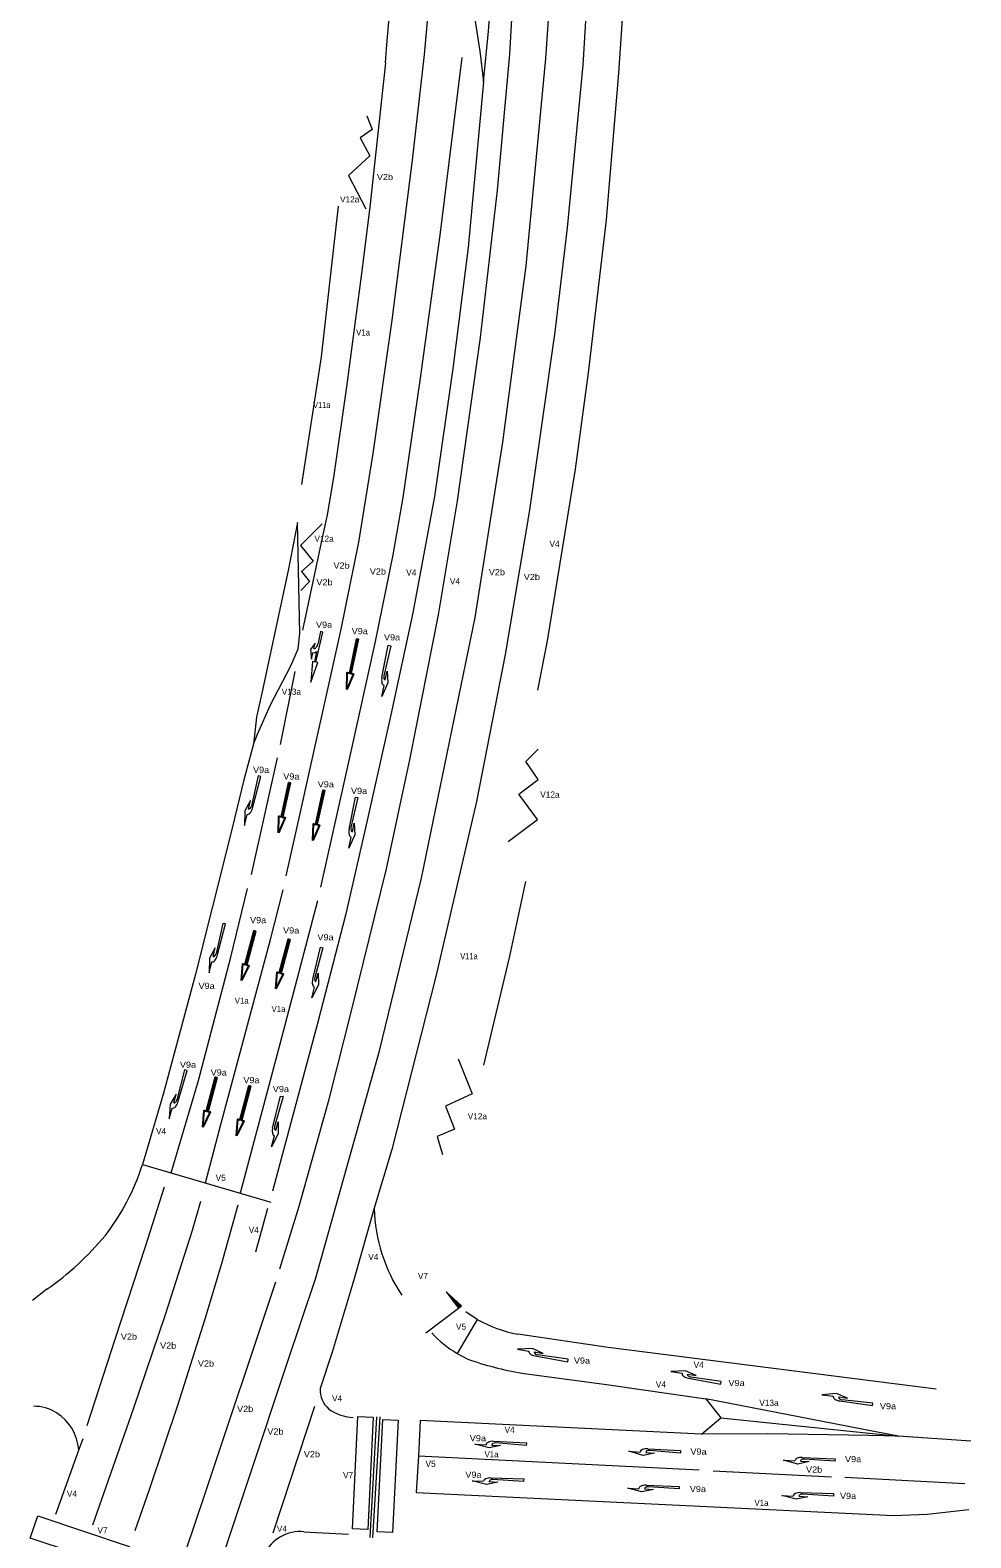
# Model space of a CAD drawing. Extents: x -598770 to -598612, y -1162818 to -1162391.
# Drawn here: x -598703.8 to -598612.3, y -1162656.8 to -1162510.2 of the extents above; entities that cross this region are included whole.
import ezdxf

# ---------------------------------------------------------------- set-up
doc = ezdxf.new("R2010")
doc.units = 0
doc.header["$LTSCALE"] = 0.24
for name, color, linetype, lineweight in [('1', 7, 'Continuous', 25), ('47', 7, 'Continuous', 13), ('48', 7, 'Continuous', 13)]:
    doc.layers.add(name, color=color, linetype=linetype, lineweight=lineweight)

msp = doc.modelspace()

# ---------------------------------------------------------------- hatches: boundary and pattern name
at = {"layer": '47'}
msp.add_hatch(color=256, dxfattribs=at).paths.add_polyline_path([(-598663.33, -1162632.866), (-598662.126, -1162634.456), (-598661.831, -1162634.21)])

# ---------------------------------------------------------------- linework, layer by layer
at = {"layer": '1'}
for points in [[(-598672.971, -1162574.273), (-598672.934, -1162572.645), (-598672.699, -1162572.695), (-598671.999, -1162569.368), (-598671.881, -1162569.392), (-598672.582, -1162572.719), (-598672.347, -1162572.769)], [(-598679.623, -1162588.236), (-598679.576, -1162586.608), (-598679.342, -1162586.659), (-598678.619, -1162583.337), (-598678.501, -1162583.363), (-598679.224, -1162586.685), (-598678.99, -1162586.736)], [(-598676.283, -1162588.976), (-598676.236, -1162587.348), (-598676.002, -1162587.399), (-598675.279, -1162584.077), (-598675.161, -1162584.103), (-598675.884, -1162587.425), (-598675.65, -1162587.476)], [(-598683.223, -1162602.59), (-598683.099, -1162600.967), (-598682.867, -1162601.029), (-598681.988, -1162597.744), (-598681.872, -1162597.776), (-598682.751, -1162601.06), (-598682.519, -1162601.122)], [(-598679.883, -1162603.4), (-598679.759, -1162601.777), (-598679.527, -1162601.839), (-598678.648, -1162598.554), (-598678.532, -1162598.586), (-598679.411, -1162601.87), (-598679.179, -1162601.932)], [(-598686.968, -1162616.841), (-598686.846, -1162615.218), (-598686.614, -1162615.28), (-598685.738, -1162611.995), (-598685.622, -1162612.025), (-598686.498, -1162615.311), (-598686.266, -1162615.372)], [(-598683.698, -1162617.691), (-598683.576, -1162616.068), (-598683.344, -1162616.13), (-598682.468, -1162612.845), (-598682.352, -1162612.875), (-598683.228, -1162616.161), (-598682.996, -1162616.222)]]:
    msp.add_lwpolyline(points, close=True, dxfattribs=at)
at = {"layer": '47'}
for p, q in [((-598669.23, -1162513.32), (-598670.74, -1162527.36)), ((-598679.44, -1162579.63), (-598678.01, -1162572.54)), ((-598669.581, -1162574.954), (-598669.354, -1162573.878)), ((-598682.24, -1162592.26), (-598679.73, -1162580.94)), ((-598682.935, -1162587.5), (-598682.677, -1162586.431)), ((-598672.789, -1162589.72), (-598672.556, -1162588.645)), ((-598686.375, -1162601.85), (-598686.117, -1162600.781)), ((-598676.395, -1162604.283), (-598676.117, -1162603.219)), ((-598690.238, -1162616.054), (-598689.948, -1162614.993)), ((-598680.3, -1162618.758), (-598680.017, -1162617.695)), ((-598692.85, -1162620.47), (-598680.36, -1162624.14)), ((-598683.59, -1162624.42), (-598685.21, -1162630.23)), ((-598680.71, -1162624.76), (-598681.86, -1162629.01)), ((-598702.14, -1162632.62), (-598703.55, -1162633.7)), ((-598665.308, -1162636.856), (-598662.126, -1162634.456)), ((-598660.32, -1162635.54), (-598662.25, -1162638.85)), ((-598660.32, -1162635.54), (-598661.42, -1162634.81)), ((-598656.378, -1162638.447), (-598655.292, -1162638.623)), ((-598662.25, -1162638.85), (-598661.29, -1162639.38)), ((-598641.481, -1162640.597), (-598640.396, -1162640.779)), ((-598626.791, -1162642.877), (-598625.7, -1162643.017)), ((-598670.108, -1162645.016), (-598670.76, -1162656.752)), ((-598670.458, -1162656.782), (-598669.752, -1162645.023)), ((-598638.51, -1162646.72), (-598665.86, -1162645.39)), ((-598612.32, -1162647.38), (-598619.36, -1162646.91)), ((-598660.539, -1162647.667), (-598659.441, -1162647.733)), ((-598645.559, -1162648.367), (-598644.461, -1162648.447)), ((-598638.72, -1162650.21), (-598666, -1162648.86)), ((-598637.36, -1162650.28), (-598625.85, -1162650.86)), ((-598630.529, -1162649.241), (-598629.431, -1162649.302)), ((-598660.799, -1162651.237), (-598659.7, -1162651.292)), ((-598624.57, -1162650.89), (-598612.9, -1162651.52)), ((-598645.679, -1162651.952), (-598644.58, -1162652.009)), ((-598630.679, -1162652.671), (-598629.58, -1162652.724)), ((-598677.15, -1162656.2), (-598672.83, -1162656.43))]:
    msp.add_line(p, q, dxfattribs=at)
for points in [[(-598678.87, -1162592.39), (-598677.52, -1162586.33), (-598673.52, -1162568.4), (-598671.82, -1162559.94), (-598670.41, -1162551.33), (-598668.56, -1162538.37), (-598666.59, -1162522.8), (-598665.43, -1162512.51), (-598664.23, -1162499.31), (-598663.42, -1162479.81), (-598663.05, -1162465.06), (-598662.73, -1162447.04), (-598662.35, -1162421.85), (-598661.61, -1162391.33)], [(-598679.49, -1162630.64), (-598677.61, -1162624.52), (-598674.71, -1162614.13), (-598672.49, -1162605.39), (-598669.14, -1162591.74), (-598666.82, -1162580.97), (-598664.07, -1162567.02), (-598662.23, -1162555.94), (-598659.99, -1162540.04), (-598658.35, -1162525.71), (-598657.15, -1162512.49), (-598656.01, -1162492.63), (-598655.18, -1162469.38), (-598654.56, -1162443.12), (-598653.84, -1162397.63)], [(-598685.18, -1162659.01), (-598682.44, -1162650.81), (-598678.78, -1162639.81), (-598676.01, -1162631.49), (-598669.81, -1162609.43), (-598665.71, -1162592.63), (-598660.52, -1162567.28), (-598657.82, -1162550.24), (-598655.55, -1162533.08), (-598653.64, -1162512.9), (-598653.24, -1162507.21), (-598652.17, -1162486.96), (-598650.81, -1162443.8), (-598650.17, -1162405.3)], [(-598646.54, -1162514.33), (-598645.68, -1162501.34), (-598645.05, -1162489.31), (-598644.56, -1162473.7), (-598643.88, -1162444.91), (-598643.66, -1162430.52), (-598643.5, -1162416.45), (-598643.38, -1162413.74)], [(-598647.05, -1162439.3), (-598647.13, -1162443.65), (-598647.86, -1162469.34), (-598648.56, -1162488.8), (-598650.03, -1162513.56), (-598651.56, -1162529.37), (-598652.75, -1162539.5), (-598655.24, -1162557.05), (-598657.58, -1162570.89), (-598660.39, -1162585.19), (-598664.32, -1162602.18), (-598668.6, -1162619.03), (-598670.31, -1162624.74)], [(-598669.23, -1162513.32), (-598669.13, -1162511.96), (-598667.99, -1162498.64), (-598668.42, -1162494.66), (-598668.51, -1162493.83), (-598670.21, -1162477.32), (-598670.5, -1162473.95), (-598670.55, -1162470), (-598670.35, -1162452.54)], [(-598675.52, -1162593.51), (-598672.68, -1162580.9), (-598670.21, -1162569.62), (-598668.47, -1162561.18), (-598667.49, -1162555.61), (-598665.84, -1162544.22), (-598663.91, -1162530.08), (-598661.76, -1162512.81)], [(-598659.7, -1162515.17), (-598661.2, -1162531.28), (-598662.68, -1162543.06), (-598664.45, -1162555.5), (-598666.55, -1162566.81), (-598668.69, -1162576.75), (-598670.99, -1162587.01), (-598673.12, -1162596.24), (-598675.8, -1162606.65), (-598680.21, -1162623.08)], [(-598654.4, -1162574.34), (-598653.46, -1162569.54), (-598650.75, -1162552.85), (-598649.48, -1162543.49), (-598647.74, -1162528.61), (-598647.6, -1162527.02), (-598646.54, -1162514.33)], [(-598670.74, -1162527.36), (-598671.57, -1162533.81), (-598673.02, -1162544.84), (-598674.29, -1162553.67), (-598674.9, -1162557.28)], [(-598674.9, -1162557.28), (-598675.37, -1162559.52), (-598677.29, -1162568.52)], [(-598676.476, -1162573.57), (-598675.815, -1162571.666), (-598675.986, -1162571.63), (-598675.312, -1162568.706), (-598675.434, -1162568.68), (-598675.556, -1162568.654), (-598675.778, -1162569.783)], [(-598676.19, -1162570.308), (-598676.075, -1162569.77), (-598676.515, -1162570.392), (-598676.409, -1162571.335), (-598676.274, -1162570.7)], [(-598675.932, -1162570.573), (-598676.133, -1162571.599), (-598676.304, -1162571.562), (-598676.476, -1162573.57)], [(-598669.573, -1162573.116), (-598668.962, -1162569.974), (-598668.718, -1162570.026), (-598669.388, -1162572.951)], [(-598669.242, -1162573.349), (-598669.064, -1162572.508), (-598668.998, -1162573.646), (-598669.581, -1162574.954)], [(-598682.06, -1162579.59), (-598683, -1162583.08), (-598684.14, -1162587.77), (-598686.06, -1162595.52), (-598687.69, -1162601.98), (-598690.81, -1162613.54), (-598692.85, -1162620.47)], [(-598682.151, -1162585.838), (-598681.348, -1162582.739), (-598681.592, -1162582.681), (-598682.247, -1162585.609)], [(-598682.55, -1162585.906), (-598682.348, -1162585.07), (-598682.898, -1162586.069), (-598682.935, -1162587.5)], [(-598672.77, -1162587.882), (-598672.142, -1162584.743), (-598671.898, -1162584.797), (-598672.584, -1162587.717)], [(-598672.441, -1162588.117), (-598672.258, -1162587.277), (-598672.199, -1162588.415), (-598672.789, -1162589.72)], [(-598690.07, -1162621.29), (-598687.4, -1162612.31), (-598684.25, -1162600.33), (-598682.63, -1162593.63)], [(-598686.73, -1162622.27), (-598685.23, -1162616.58), (-598680.4, -1162598.6), (-598679.18, -1162593.78)], [(-598675.82, -1162594.82), (-598679.49, -1162608.78), (-598683.36, -1162623.26)], [(-598685.591, -1162600.188), (-598684.788, -1162597.089), (-598685.032, -1162597.031), (-598685.687, -1162599.959)], [(-598685.99, -1162600.256), (-598685.788, -1162599.42), (-598686.338, -1162600.419), (-598686.375, -1162601.85)], [(-598676.299, -1162602.448), (-598675.541, -1162599.338), (-598675.299, -1162599.402), (-598676.107, -1162602.291)], [(-598675.98, -1162602.697), (-598675.762, -1162601.865), (-598675.75, -1162603.005), (-598676.395, -1162604.283)], [(-598689.404, -1162614.416), (-598688.509, -1162611.343), (-598688.751, -1162611.277), (-598689.494, -1162614.184)], [(-598689.805, -1162614.472), (-598689.579, -1162613.642), (-598690.158, -1162614.624), (-598690.238, -1162616.054)], [(-598680.195, -1162616.923), (-598679.421, -1162613.818), (-598679.179, -1162613.882), (-598680.002, -1162616.768)], [(-598679.877, -1162617.174), (-598679.655, -1162616.343), (-598679.649, -1162617.483), (-598680.3, -1162618.758)], [(-598698.24, -1162645.87), (-598695.48, -1162637.38), (-598692.57, -1162628.46), (-598690.7, -1162622.66)], [(-598687.22, -1162624.09), (-598688.01, -1162626.91), (-598690.63, -1162635.09), (-598693.75, -1162644.29), (-598697.72, -1162655.57)], [(-598670.31, -1162624.74), (-598672.25, -1162631.48), (-598672.65, -1162632.89)], [(-598685.21, -1162630.23), (-598686.79, -1162635.51), (-598689.42, -1162643.81), (-598692.15, -1162652.01), (-598693.6, -1162656.11)], [(-598688.64, -1162658.06), (-598686.79, -1162652.59), (-598679.89, -1162631.9)], [(-598672.65, -1162632.89), (-598674.4, -1162638.73), (-598675.59, -1162642.28)], [(-598615.7, -1162642.34), (-598647.59, -1162638.27), (-598656.35, -1162636.98)], [(-598654.759, -1162638.709), (-598653.91, -1162638.846), (-598654.948, -1162638.374), (-598656.378, -1162638.447)], [(-598654.661, -1162639.101), (-598651.51, -1162639.663), (-598651.47, -1162639.417), (-598654.44, -1162638.988)], [(-598655.96, -1162640.77), (-598647.73, -1162641.87), (-598638.08, -1162643.28)], [(-598639.864, -1162640.868), (-598639.016, -1162641.011), (-598640.051, -1162640.533), (-598641.481, -1162640.597)], [(-598639.767, -1162641.261), (-598636.62, -1162641.844), (-598636.579, -1162641.597), (-598639.546, -1162641.15)], [(-598625.165, -1162643.086), (-598624.312, -1162643.195), (-598625.365, -1162642.758), (-598626.791, -1162642.877)], [(-598680.14, -1162656.31), (-598679.23, -1162653.55), (-598676.09, -1162643.98)], [(-598625.053, -1162643.475), (-598621.886, -1162643.934), (-598621.854, -1162643.686), (-598624.836, -1162643.355)], [(-598665.86, -1162645.39), (-598666, -1162648.86), (-598666.23, -1162652.38)], [(-598698.65, -1162647.17), (-598699.05, -1162648.21), (-598701.29, -1162654.52)], [(-598658.902, -1162647.766), (-598658.044, -1162647.818), (-598659.16, -1162648.051), (-598660.539, -1162647.667)], [(-598658.72, -1162647.404), (-598655.522, -1162647.545), (-598655.538, -1162647.795), (-598658.529, -1162647.563)], [(-598643.923, -1162648.486), (-598643.065, -1162648.548), (-598644.184, -1162648.768), (-598645.559, -1162648.367)], [(-598643.736, -1162648.126), (-598640.541, -1162648.305), (-598640.559, -1162648.555), (-598643.548, -1162648.287)], [(-598628.891, -1162649.332), (-598628.033, -1162649.38), (-598629.148, -1162649.619), (-598630.529, -1162649.241)], [(-598628.711, -1162648.97), (-598625.513, -1162649.095), (-598625.527, -1162649.345), (-598628.52, -1162649.128)], [(-598659.161, -1162651.32), (-598658.302, -1162651.363), (-598659.416, -1162651.607), (-598660.799, -1162651.237)], [(-598658.982, -1162650.956), (-598655.784, -1162651.065), (-598655.796, -1162651.315), (-598658.79, -1162651.113)], [(-598643.862, -1162651.673), (-598640.664, -1162651.785), (-598640.676, -1162652.035), (-598643.67, -1162651.83)], [(-598666.23, -1162652.38), (-598623.19, -1162654.47), (-598619.84, -1162654.62), (-598616.55, -1162654.49), (-598612.52, -1162654.04)], [(-598644.041, -1162652.037), (-598643.182, -1162652.081), (-598644.296, -1162652.324), (-598645.679, -1162651.952)], [(-598629.04, -1162652.749), (-598628.181, -1162652.79), (-598629.295, -1162653.038), (-598630.679, -1162652.671)], [(-598628.863, -1162652.385), (-598625.664, -1162652.485), (-598625.676, -1162652.735), (-598628.67, -1162652.542)]]:
    msp.add_lwpolyline(points, dxfattribs=at)
for points in [[(-598659.74, -1162480.57), (-598660.04, -1162488.91), (-598660.27, -1162492.9), (-598660.68, -1162500.88), (-598661.01, -1162505.9), (-598660.06, -1162512.2), (-598659.7, -1162515.17), (-598659.2, -1162510.24), (-598658.47, -1162500.66), (-598659.18, -1162488.38)], [(-598677.77, -1162558.05), (-598678.7, -1162562.71), (-598680.08, -1162569.19), (-598681.19, -1162574.36), (-598681.77, -1162576.97), (-598682.06, -1162579.59), (-598681.68, -1162578.63), (-598680.4, -1162575.78), (-598678.44, -1162571.97), (-598677.71, -1162570.33), (-598677.55, -1162568.82)], [(-598663.33, -1162632.866), (-598662.126, -1162634.456), (-598661.831, -1162634.21)], [(-598636.63, -1162645.12), (-598619.36, -1162646.91), (-598622.22, -1162646.34), (-598638.08, -1162643.28)], [(-598671.918, -1162644.987), (-598670.414, -1162645.064), (-598670.946, -1162655.991), (-598672.441, -1162655.914)], [(-598669.498, -1162645.276), (-598667.994, -1162645.353), (-598668.526, -1162656.28), (-598670.021, -1162656.203)], [(-598636.63, -1162645.12), (-598619.36, -1162646.91), (-598622.23, -1162646.83), (-598632.06, -1162646.69), (-598638.51, -1162646.72)], [(-598703.027, -1162654.647), (-598694.128, -1162657.617), (-598694.848, -1162659.777), (-598703.766, -1162656.807)]]:
    msp.add_lwpolyline(points, close=True, dxfattribs=at)
for centre, radius, start, end in [((-598713.6451, -1162613.9876), 21.7821, 321.95997, 342.6864), ((-598654.5208, -1162624.3927), 15.793, 181.26003, 213.8948), ((-598719.1139, -1162608.5441), 29.4578, 305.18436, 320.17543), ((-598653.8954, -1162624.0202), 13.1903, 240.8515, 259.27502), ((-598657.5058, -1162630.4657), 9.6334, 221.50762, 240.49704), ((-598651.0983, -1162611.2135), 29.9537, 250.10791, 260.6591), ((-598673.0575, -1162642.3653), 2.5339, 178.07143, 228.39559), ((-598703.3569, -1162647.9816), 3.9827, 57.03786, 91.3394), ((-598672.1663, -1162640.6517), 4.4321, 234.50108, 267.62512), ((-598703.6699, -1162648.5529), 4.6326, 4.24542, 57.63488), ((-598677.536, -1162659.9634), 3.7832, 84.1441, 155.92246)]:
    msp.add_arc(centre, radius, start, end, dxfattribs=at)
for centre, major_axis, ratio, start_param, end_param in [((-598676.2317, -1162570.5042), (0.3012, -0.0642), 0.649351, 4.71238898, 6.28318531), ((-598676.0649, -1162569.7217), (0.1251, 0.5868), 0.49, 3.14159265, 4.71238898), ((-598669.2086, -1162573.1926), (-0.1449, -0.6848), 0.531429, 4.71238898, 6.28318531), ((-598669.1672, -1162572.9969), (-0.0745, -0.3522), 0.625, 4.71238898, 6.28318531), ((-598682.4657, -1162585.556), (0.0845, 0.3499), 0.625, 3.14159265, 4.71238898), ((-598682.5126, -1162585.7504), (0.1642, 0.6805), 0.531429, 3.14159265, 4.71238898), ((-598672.4067, -1162587.9605), (-0.1488, -0.684), 0.531429, 4.71238898, 6.28318531), ((-598672.3642, -1162587.765), (-0.0765, -0.3518), 0.625, 4.71238898, 6.28318531), ((-598685.9526, -1162600.1004), (0.1642, 0.6805), 0.531429, 3.14159265, 4.71238898), ((-598685.9057, -1162599.906), (0.0845, 0.3499), 0.625, 3.14159265, 4.71238898), ((-598675.9392, -1162602.5416), (-0.1771, -0.6772), 0.531429, 4.71238898, 6.28318531), ((-598675.8886, -1162602.3481), (-0.0911, -0.3483), 0.625, 4.71238898, 6.28318531), ((-598689.7634, -1162614.3177), (0.1846, 0.6752), 0.531429, 3.14159265, 4.71238898), ((-598689.7107, -1162614.1248), (0.0949, 0.3473), 0.625, 3.14159265, 4.71238898), ((-598679.8357, -1162617.0188), (0.1806, 0.6763), 0.531429, 1.57079633, 3.14159265), ((-598679.7841, -1162616.8256), (0.0929, 0.3478), 0.625, 1.57079633, 3.14159265), ((-598654.6015, -1162638.7339), (0.6911, -0.1115), 0.531429, 3.14159265, 4.71238898), ((-598654.404, -1162638.7658), (0.3554, -0.0574), 0.625, 3.14159265, 4.71238898), ((-598639.706, -1162640.8945), (0.6903, -0.1159), 0.531429, 3.14159265, 4.71238898), ((-598639.5088, -1162640.9276), (0.355, -0.0596), 0.625, 3.14159265, 4.71238898), ((-598625.0061, -1162643.1059), (0.6943, -0.0889), 0.531429, 3.14159265, 4.71238898), ((-598624.8077, -1162643.1313), (0.3571, -0.0457), 0.625, 3.14159265, 4.71238898), ((-598658.7421, -1162647.776), (-0.6987, 0.0424), 0.531429, 4.71238898, 6.28318531), ((-598658.5424, -1162647.7881), (-0.3593, 0.0218), 0.625, 4.71238898, 6.28318531), ((-598643.7631, -1162648.4975), (0.6982, -0.0507), 0.531429, 1.57079633, 3.14159265), ((-598643.5636, -1162648.512), (0.3591, -0.0261), 0.625, 1.57079633, 3.14159265), ((-598628.7315, -1162649.3416), (-0.6989, 0.039), 0.531429, 4.71238898, 6.28318531), ((-598628.5318, -1162649.3527), (-0.3594, 0.02), 0.625, 4.71238898, 6.28318531), ((-598659.0008, -1162651.328), (0.6991, -0.0354), 0.531429, 1.57079633, 3.14159265), ((-598658.8011, -1162651.3381), (0.3595, -0.0182), 0.625, 1.57079633, 3.14159265), ((-598643.881, -1162652.045), (-0.6991, 0.036), 0.531429, 4.71238898, 6.28318531), ((-598643.6812, -1162652.0553), (-0.3595, 0.0185), 0.625, 4.71238898, 6.28318531), ((-598628.8804, -1162652.7572), (0.6992, -0.0334), 0.531429, 1.57079633, 3.14159265), ((-598628.6807, -1162652.7667), (0.3596, -0.0172), 0.625, 1.57079633, 3.14159265)]:
    msp.add_ellipse(centre, major_axis=major_axis, ratio=ratio, start_param=start_param, end_param=end_param, dxfattribs=at)
at = {"layer": '48'}
for points in [[(-598671.04, -1162518.49), (-598670.52, -1162519.82), (-598671.67, -1162520.63), (-598670.74, -1162522.39), (-598672.81, -1162524.29), (-598671.15, -1162527.54)], [(-598673.83, -1162527.28), (-598675.49, -1162541.94), (-598677.39, -1162554.36)], [(-598675.38, -1162558.16), (-598677.49, -1162560.27), (-598676.24, -1162561.79), (-598677.38, -1162562.82), (-598676.62, -1162563.79), (-598677.44, -1162564.66)], [(-598657.3, -1162589.08), (-598654.44, -1162586.91), (-598656.27, -1162584.45), (-598654.38, -1162583.05), (-598655.59, -1162581.3), (-598654.38, -1162580.07)], [(-598659.67, -1162610.82), (-598657.14, -1162600.21), (-598655.57, -1162592.96)], [(-598662.17, -1162610.21), (-598660.8, -1162613.61), (-598663.38, -1162614.81), (-598662.52, -1162617.05), (-598664.2, -1162617.75), (-598663.67, -1162619.52)]]:
    msp.add_lwpolyline(points, dxfattribs=at)

# ---------------------------------------------------------------- texts
at = {"layer": '47'}
for s, width, p in [('V2b', 1.1, (-598670.06, -1162524.74)), ('V1a', 0.95, (-598672.08, -1162539.86)), ('V2b', 1.1, (-598674.28, -1162562.53)), ('V2b', 1.1, (-598675.94, -1162564.15)), ('V2b', 1.1, (-598670.75, -1162563.1)), ('V2b', 1.1, (-598659.18, -1162563.17)), ('V2b', 1.1, (-598655.78, -1162563.64)), ('V9a', 1.1, (-598675.98, -1162568.28)), ('V9a', 1.1, (-598672.51, -1162568.91)), ('V9a', 1.1, (-598669.37, -1162569.51)), ('V9a', 1.1, (-598682.1, -1162582.4)), ('V9a', 1.1, (-598679.16, -1162583.04)), ('V9a', 1.1, (-598675.81, -1162583.8)), ('V9a', 1.1, (-598672.58, -1162584.44)), ('V9a', 1.1, (-598682.39, -1162597.01)), ('V9a', 1.1, (-598679.18, -1162598.01)), ('V9a', 1.1, (-598675.84, -1162598.68)), ('V9a', 1.1, (-598687.4, -1162603.41)), ('V1a', 0.95, (-598683.88, -1162604.85)), ('V1a', 0.95, (-598680.3, -1162605.65)), ('V9a', 1.1, (-598689.21, -1162611.07)), ('V9a', 1.1, (-598686.22, -1162611.83)), ('V9a', 1.1, (-598683.04, -1162612.57)), ('V9a', 1.1, (-598680.18, -1162613.44)), ('V2b', 1.1, (-598694.95, -1162637.52)), ('V2b', 1.1, (-598691.14, -1162638.39)), ('V2b', 1.1, (-598687.46, -1162640.13)), ('V9a', 1.1, (-598650.91, -1162639.85)), ('V9a', 1.1, (-598635.88, -1162642.03)), ('V2b', 1.1, (-598683.65, -1162644.55)), ('V9a', 1.1, (-598621.16, -1162644.28)), ('V2b', 1.1, (-598680.71, -1162646.75)), ('V9a', 1.1, (-598661.03, -1162647.4)), ('V2b', 1.1, (-598677.16, -1162648.96)), ('V1a', 0.95, (-598659.59, -1162648.96)), ('V9a', 1.1, (-598639.58, -1162648.7)), ('V9a', 1.1, (-598624.55, -1162649.43)), ('V2b', 1.1, (-598628.34, -1162650.45)), ('V9a', 1.1, (-598661.46, -1162650.95)), ('V9a', 1.1, (-598639.64, -1162652.34)), ('V1a', 0.95, (-598633.35, -1162653.69)), ('V9a', 1.1, (-598625.04, -1162653.01))]:
    msp.add_text(s, height=0.6, dxfattribs=dict(at, width=width)).set_placement(p)
for s, p in [('V4', (-598653.28, -1162560.42)), ('V4', (-598667.21, -1162563.21)), ('V4', (-598662.97, -1162564.06)), ('V13a', (-598679.31, -1162574.8)), ('V4', (-598691.53, -1162617.54)), ('V5', (-598685.73, -1162622.07)), ('V4', (-598682.52, -1162627.14)), ('V4', (-598670.9, -1162629.77)), ('V7', (-598666.07, -1162631.62)), ('V5', (-598662.37, -1162636.55)), ('V4', (-598639.27, -1162640.26)), ('V4', (-598674.42, -1162643.53)), ('V4', (-598642.94, -1162642.17)), ('V13a', (-598632.88, -1162643.96)), ('V4', (-598657.65, -1162646.58)), ('V5', (-598665.33, -1162649.89)), ('V7', (-598673.35, -1162651)), ('V4', (-598700.2, -1162652.8)), ('V7', (-598697.22, -1162656.36)), ('V4', (-598679.78, -1162656.2))]:
    msp.add_text(s, height=0.6, dxfattribs=at).set_placement(p)
at = {"layer": '48'}
for p in [(-598673.64, -1162526.91), (-598676.13, -1162559.92), (-598654.18, -1162584.8), (-598661.23, -1162616.09)]:
    msp.add_text('V12a', height=0.6, dxfattribs=at).set_placement(p)
at = {"layer": '48', "width": 0.9}
for p in [(-598676.26, -1162546.91), (-598661.95, -1162600.52)]:
    msp.add_text('V11a', height=0.6, dxfattribs=at).set_placement(p)

doc.saveas('drawing.dxf')
